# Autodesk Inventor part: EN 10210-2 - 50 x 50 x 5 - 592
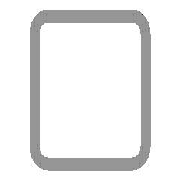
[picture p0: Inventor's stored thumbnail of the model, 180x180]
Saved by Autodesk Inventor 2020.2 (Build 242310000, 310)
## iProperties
_CCFamilyMember: 16
_CCFamilyDisplayName: DIN EN 10210-2 (USAS B17.1 quadratisch) - Rohrleitung — In Klammern angegebene Größen wurden aufgehoben
_FrameMemberDoc: Frame Member File
_Version: 15.0.0
_GetPNFromCC: 1
IsCustomPart: 1
Created: 2019-01
Part Number: EN 10210-2 - 50 x 50 x 5 - 592
Material: Stahl, weich
Description: Rohrleitung
Document SubType Name: Modeling
Standard: DIN
Designer: lutzd
Standard Revision: 2006-07
Standards Organization: DIN
Language: de-DE
Size Designation: 50 x 50 x 5
Categories: <MemberInstance><Categories><Category DisplayName="Profile" InternalName="089c4875-fa83-4c05-b084-43b9cc11f5ed" Mnemonic="GRDR"><CategoryParameter DisplayName="
Stock Number: 50 x 50 x 5
Mass: 4057.82 g
Surface Area: 2021.62 cm^2
Volume: 516.919 cm^3
Density: 7.85 g/cm^3
Appearance: Semi-Polished(8)
G_L: 592,000 mm
G_W: 50,000 mm
G_H: 50,000 mm
DocNumber: ADSK-014280
Folder: .
Dimensions: 50x50x592 mm
Mass: 4,058 kg
+C712E655-CCB9-4DCA-AEEF-10B069224B02+SCHNITTDETAIL1: Schnittwinkel 90,00 grd
+9E6E871D-FE55-4977-9548-49DB52EF8BE9+SCHNITTDETAIL2: Schnittwinkel 90,00 grd
VLT_Material: Stahl, weich
Title: Profil-Bauteil
Author: lutzd
Revision Number: -
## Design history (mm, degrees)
node "Startebene"
node "Endebene"
sketch "Skizze"
  geometry: L1 (-25, -17.5)-(-25, 17.5); L2 (-17.5, 25)-(17.5, 25); L3 (25, 17.5)-(25, -17.5); L4 (17.5, -25)-(-17.5, -25); L5 (-15, 20)-(15, 20); L6 (20, 15)-(20, -15); L7 (15, -20)-(-15, -20); L8 (-20, -15)-(-20, 15); L9 (0, 37.175)-(0, -37.175) reference; L10 (-37.175, 0)-(37.175, 0) reference; A1 r 7.5 centre (-17.5, -17.5) between (-25, -17.5) and (-17.5, -25); A2 r 7.5 centre (-17.5, 17.5) between (-17.5, 25) and (-25, 17.5); A3 r 7.5 centre (17.5, 17.5) between (25, 17.5) and (17.5, 25); A4 r 7.5 centre (17.5, -17.5) between (17.5, -25) and (25, -17.5); A5 r 5 centre (-15, -15) between (-20, -15) and (-15, -20); A6 r 5 centre (-15, 15) between (-15, 20) and (-20, 15); A7 r 5 centre (15, 15) between (20, 15) and (15, 20); A8 r 5 centre (15, -15) between (15, -20) and (20, -15)
  constraints: 16 end point, 16 point on circle, 16 tangent, 8 centre point, 6 equal radius, 4 parallel, 2 perpendicular, 2 other
  dimensions: "d7" = 7.5 radius of A1 (= G_IR); "d10" = 50 distance between parallel lines of L2 L4 (= G_H); "d11" = 50 distance between parallel lines of L1 L3 (= G_W); "d12" = 5 distance between parallel lines of L3 L6 (= G_T); "d15" = 25 distance between parallel lines of L2 L10 (= 0.5 x d10); "d16" = 25 distance between parallel lines of L9 L3 (= 0.5 x d11); "d19" = 5 radius of A5 (= G_T); "d20" = 5 distance between parallel lines of L4 L7 (= G_T)
extrude "Körper" new body sketch "Skizze" stored distance "d3" = 592 (= G_L); taper "d4" = 0 deg
node "Driven Length"
  sketch "Sketch3"
    geometry: L1 (0, 0)-(10, 0) reference
    constraints: 2 end point, 1 horizontal
  workplane "Work Plane3"
  sketch "Sketch4"
    geometry: L1 (-2, 25)-(12, 25) reference; L2 (-2, 617)-(12, 617) reference
    dimensions: "d18" = 592 distance between parallel lines of L1 L2 (derived)
workplane "Arbeitsebene4"
feature "Trennen1"
workplane "Arbeitsebene5"
feature "Trennen2"
body "Solid1"
other parameters: "G_W" = 50 [user parameter; used in 1 equation term], "G_H" = 50 [user parameter; used in 1 equation term], "G_T" = 5 [user parameter; used in 3 equation terms], "G_IR" = 7.5 [user parameter; used in 1 equation term], "G_L" = 592 (= d18) [user parameter; used in 1 equation term], "G_OFFSET_START" = -25 [user parameter; used in 1 equation term], "d13" = 25 (= -G_OFFSET_START), "d14" = 617 (= G_OFFSET_END + B_L), "B_L" = 667 [user parameter; used in 1 equation term], "d17" = 90 deg
